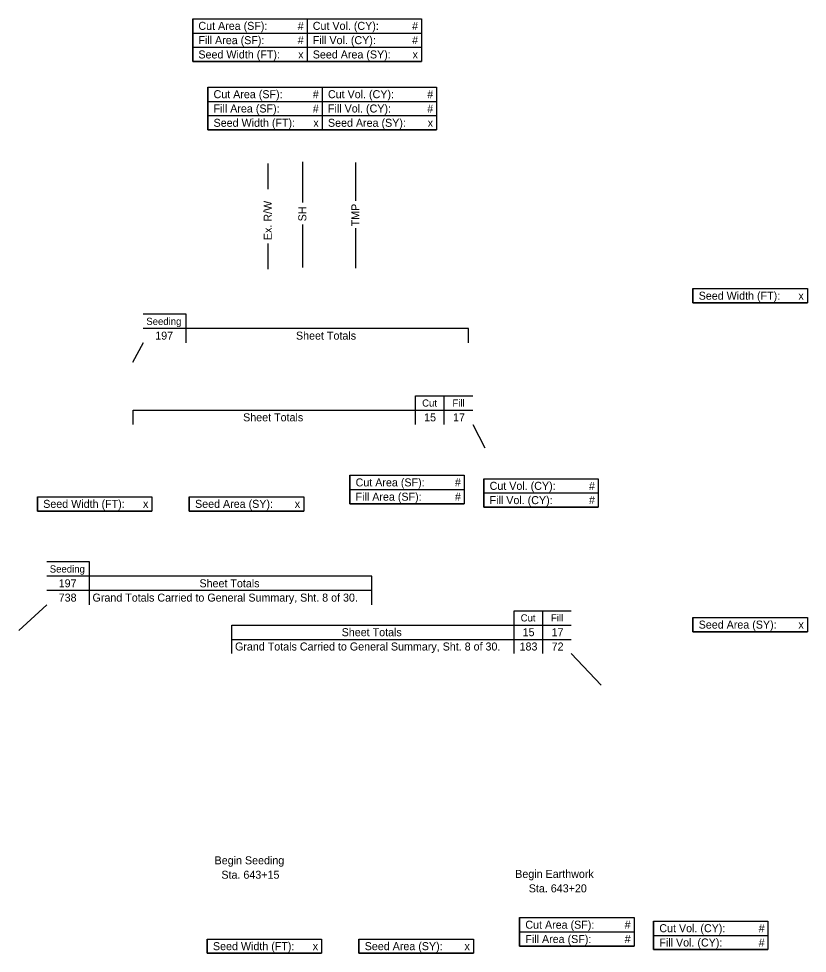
# Model space of a CAD drawing. Extents: x -46 to 154, y -27 to 78.
# Drawn here: x 135.55 to 149.34, y 55.78 to 72.12 of the extents above; entities that cross this region are included whole.
import ezdxf

# ---------------------------------------------------------------- set-up
doc = ezdxf.new("R2010")
doc.units = 0
for name, color, linetype in [('Default', 7, 'Continuous'), ('DT_X_Contour_Minor', 7, 'Continuous'), ('DT_X_Void', 7, 'Continuous'), ('PV_X_Shoulder', 7, 'Continuous'), ('RD_X_GR_Lt', 7, 'Continuous'), ('SH_Text', 7, 'Continuous'), ('SV_X_Top_of_Bank', 7, 'Continuous'), ('UT_X_Telecom', 7, 'Continuous')]:
    doc.layers.add(name, color=color, linetype=linetype)

msp = doc.modelspace()

# ---------------------------------------------------------------- linework, layer by layer
at = {"layer": 'Default'}
for p, q in [((138.482, 66.455), (138.482, 66.955)), ((143.418, 66.455), (143.418, 66.705)), ((142.494, 65.027), (142.494, 65.527)), ((142.994, 65.027), (142.994, 65.527)), ((137.558, 65.027), (137.558, 65.277)), ((136.794, 61.875), (136.794, 62.625)), ((141.73, 61.875), (141.73, 62.375)), ((136.044, 61.875), (135.554, 61.423)), ((144.217, 61.02), (144.217, 61.77)), ((144.717, 61.02), (144.717, 61.77)), ((139.281, 61.02), (139.281, 61.52)), ((144.217, 61.02), (144.217, 61.52)), ((145.217, 61.02), (145.741, 60.471))]:
    msp.add_line(p, q, dxfattribs=at)
at = {"layer": 'DT_X_Contour_Minor'}
for p, q in [((138.597, 72.121), (142.597, 72.121)), ((138.597, 72.121), (138.597, 71.371)), ((140.597, 72.121), (140.597, 71.371)), ((142.597, 72.121), (142.597, 71.371)), ((138.597, 71.871), (142.597, 71.871)), ((138.597, 71.621), (142.597, 71.621)), ((138.597, 71.371), (142.597, 71.371)), ((138.862, 70.926), (142.862, 70.926)), ((138.862, 70.926), (138.862, 70.176)), ((140.862, 70.926), (140.862, 70.176)), ((142.862, 70.926), (142.862, 70.176)), ((138.862, 70.676), (142.862, 70.676)), ((138.862, 70.426), (142.862, 70.426)), ((138.862, 70.176), (142.862, 70.176)), ((147.345, 67.403), (149.345, 67.403)), ((147.345, 67.403), (147.345, 67.153)), ((149.345, 67.403), (149.345, 67.153)), ((147.345, 67.153), (149.345, 67.153)), ((138.482, 66.955), (137.732, 66.955)), ((143.418, 66.705), (137.732, 66.705)), ((142.494, 65.527), (143.494, 65.527)), ((137.558, 65.277), (143.494, 65.277)), ((141.346, 64.139), (143.346, 64.139)), ((141.346, 64.139), (141.346, 63.639)), ((143.346, 64.139), (143.346, 63.639)), ((143.689, 64.079), (145.689, 64.079)), ((143.689, 64.079), (143.689, 63.579)), ((145.689, 64.079), (145.689, 63.579)), ((135.883, 63.764), (137.883, 63.764)), ((135.883, 63.764), (135.883, 63.514)), ((137.883, 63.764), (137.883, 63.514)), ((138.538, 63.764), (140.538, 63.764)), ((138.538, 63.764), (138.538, 63.514)), ((140.538, 63.764), (140.538, 63.514)), ((141.346, 63.889), (143.346, 63.889)), ((143.689, 63.829), (145.689, 63.829)), ((141.346, 63.639), (143.346, 63.639)), ((143.689, 63.579), (145.689, 63.579)), ((135.883, 63.514), (137.883, 63.514)), ((138.538, 63.514), (140.538, 63.514)), ((136.794, 62.625), (136.044, 62.625)), ((141.73, 62.375), (136.044, 62.375)), ((141.73, 62.125), (136.044, 62.125)), ((144.217, 61.77), (145.217, 61.77)), ((147.345, 61.653), (149.345, 61.653)), ((147.345, 61.653), (147.345, 61.403)), ((149.345, 61.653), (149.345, 61.403)), ((139.281, 61.52), (145.217, 61.52)), ((147.345, 61.403), (149.345, 61.403)), ((139.281, 61.27), (145.217, 61.27)), ((144.314, 56.406), (146.314, 56.406)), ((144.314, 56.406), (144.314, 55.906)), ((146.314, 56.406), (146.314, 55.906)), ((146.657, 56.345), (148.657, 56.345)), ((146.657, 56.345), (146.657, 55.845)), ((148.657, 56.345), (148.657, 55.845)), ((144.314, 56.156), (146.314, 56.156)), ((146.657, 56.095), (148.657, 56.095)), ((138.851, 56.031), (140.851, 56.031)), ((138.851, 56.031), (138.851, 55.781)), ((140.851, 56.031), (140.851, 55.781)), ((141.505, 56.031), (143.505, 56.031)), ((141.505, 56.031), (141.505, 55.781)), ((143.505, 56.031), (143.505, 55.781)), ((144.314, 55.906), (146.314, 55.906)), ((138.851, 55.781), (140.851, 55.781)), ((141.505, 55.781), (143.505, 55.781)), ((146.657, 55.845), (148.657, 55.845))]:
    msp.add_line(p, q, dxfattribs=at)
at = {"layer": 'PV_X_Shoulder'}
for p, q in [((139.919, 69.143), (139.919, 69.59)), ((139.919, 67.744), (139.919, 68.191))]:
    msp.add_line(p, q, dxfattribs=at)
at = {"layer": 'RD_X_GR_Lt'}
for p, q in [((140.525, 68.908), (140.525, 69.62)), ((140.525, 67.774), (140.525, 68.521))]:
    msp.add_line(p, q, dxfattribs=at)
at = {"layer": 'SH_Text'}
for points in [[(138.597, 72.121), (142.597, 72.121), (142.597, 71.371), (138.597, 71.371)], [(138.862, 70.926), (142.862, 70.926), (142.862, 70.176), (138.862, 70.176)], [(147.345, 67.403), (149.345, 67.403), (149.345, 67.153), (147.345, 67.153)], [(141.346, 64.139), (143.346, 64.139), (143.346, 63.639), (141.346, 63.639)], [(143.689, 64.079), (145.689, 64.079), (145.689, 63.579), (143.689, 63.579)], [(135.883, 63.764), (137.883, 63.764), (137.883, 63.514), (135.883, 63.514)], [(138.538, 63.764), (140.538, 63.764), (140.538, 63.514), (138.538, 63.514)], [(147.345, 61.653), (149.345, 61.653), (149.345, 61.403), (147.345, 61.403)], [(144.314, 56.406), (146.314, 56.406), (146.314, 55.906), (144.314, 55.906)], [(146.657, 56.345), (148.657, 56.345), (148.657, 55.845), (146.657, 55.845)], [(138.851, 56.031), (140.851, 56.031), (140.851, 55.781), (138.851, 55.781)], [(141.505, 56.031), (143.505, 56.031), (143.505, 55.781), (141.505, 55.781)]]:
    msp.add_lwpolyline(points, close=True, dxfattribs=at)
at = {"layer": 'SV_X_Top_of_Bank'}
for p, q in [((141.452, 68.936), (141.452, 69.606)), ((141.452, 67.76), (141.452, 68.461))]:
    msp.add_line(p, q, dxfattribs=at)
at = {"layer": 'UT_X_Telecom'}
for p, q in [((137.732, 66.455), (137.545, 66.112)), ((143.494, 65.027), (143.706, 64.619))]:
    msp.add_line(p, q, dxfattribs=at)

# ---------------------------------------------------------------- texts
at = {"layer": 'Default'}
for s, height, p in [('Seeding', 0.125, (137.786, 66.767)), ('197', 0.14, (137.942, 66.51)), ('Sheet Totals', 0.14, (140.403, 66.51)), ('Cut', 0.125, (142.609, 65.339)), ('Fill', 0.125, (143.139, 65.339)), ('Sheet Totals', 0.14, (139.479, 65.082)), ('15', 0.14, (142.644, 65.082)), ('17', 0.14, (143.15, 65.082)), ('Seeding', 0.125, (136.098, 62.438)), ('197', 0.14, (136.254, 62.18)), ('Sheet Totals', 0.14, (138.715, 62.18)), ('738', 0.14, (136.254, 61.93)), ('Grand Totals Carried to General Summary, Sht. 8 of 30.', 0.14, (136.845, 61.93)), ('Cut', 0.125, (144.332, 61.583)), ('Fill', 0.125, (144.862, 61.583)), ('Sheet Totals', 0.14, (141.202, 61.325)), ('15', 0.14, (144.367, 61.325)), ('17', 0.14, (144.873, 61.325)), ('Grand Totals Carried to General Summary, Sht. 8 of 30.', 0.14, (139.337, 61.075)), ('183', 0.14, (144.313, 61.075)), ('72', 0.14, (144.874, 61.075))]:
    msp.add_text(s, height=height, dxfattribs=at).set_placement(p)
at = {"layer": 'DT_X_Void'}
for s, p in [('Cut Area (SF):', (138.697, 71.926)), ('#', (140.434, 71.926)), ('Cut Vol. (CY):', (140.697, 71.926)), ('#', (142.434, 71.926)), ('Fill Area (SF):', (138.697, 71.676)), ('#', (140.434, 71.676)), ('Fill Vol. (CY):', (140.697, 71.676)), ('#', (142.434, 71.676)), ('Seed Width (FT):', (138.697, 71.426)), ('Seed Area (SY):', (140.697, 71.426)), ('x', (140.442, 71.426)), ('x', (142.442, 71.426)), ('Cut Area (SF):', (138.962, 70.731)), ('#', (140.698, 70.731)), ('Cut Vol. (CY):', (140.962, 70.731)), ('#', (142.698, 70.731)), ('Fill Area (SF):', (138.962, 70.481)), ('#', (140.698, 70.481)), ('Fill Vol. (CY):', (140.962, 70.481)), ('#', (142.698, 70.481)), ('Seed Width (FT):', (138.962, 70.231)), ('x', (140.707, 70.231)), ('Seed Area (SY):', (140.962, 70.231)), ('x', (142.707, 70.231)), ('Seed Width (FT):', (147.445, 67.208)), ('x', (149.189, 67.208)), ('Cut Area (SF):', (141.446, 63.944)), ('#', (143.182, 63.944)), ('Cut Vol. (CY):', (143.789, 63.884)), ('#', (145.526, 63.884)), ('Fill Area (SF):', (141.446, 63.694)), ('#', (143.182, 63.694)), ('Fill Vol. (CY):', (143.789, 63.634)), ('#', (145.526, 63.634)), ('Seed Width (FT):', (135.983, 63.569)), ('x', (137.728, 63.569)), ('Seed Area (SY):', (138.638, 63.569)), ('x', (140.382, 63.569)), ('Seed Area (SY):', (147.445, 61.458)), ('x', (149.189, 61.458)), ('Begin Seeding', (138.98, 57.337)), ('Sta. 643+15', (139.099, 57.085)), ('Begin Earthwork', (144.237, 57.099)), ('Sta. 643+20', (144.474, 56.847)), ('Cut Area (SF):', (144.414, 56.211)), ('#', (146.15, 56.211)), ('Cut Vol. (CY):', (146.757, 56.15)), ('#', (148.494, 56.15)), ('Fill Area (SF):', (144.414, 55.961)), ('#', (146.15, 55.961)), ('Fill Vol. (CY):', (146.757, 55.9)), ('Seed Width (FT):', (138.951, 55.836)), ('x', (140.696, 55.836)), ('Seed Area (SY):', (141.605, 55.836)), ('x', (143.35, 55.836)), ('#', (148.494, 55.9))]:
    msp.add_text(s, height=0.14, dxfattribs=at).set_placement(p)
at = {"layer": 'PV_X_Shoulder'}
msp.add_text('Ex. R/W', height=0.14, rotation=90, dxfattribs=at).set_placement((139.979, 68.25))
at = {"layer": 'RD_X_GR_Lt'}
msp.add_text('SH', height=0.14, rotation=90, dxfattribs=at).set_placement((140.584, 68.578))
at = {"layer": 'SV_X_Top_of_Bank'}
msp.add_text('TMP', height=0.14, rotation=90, dxfattribs=at).set_placement((141.511, 68.49))

doc.saveas('drawing.dxf')
